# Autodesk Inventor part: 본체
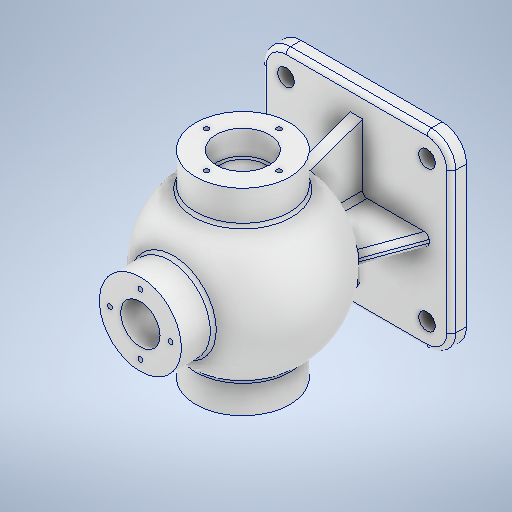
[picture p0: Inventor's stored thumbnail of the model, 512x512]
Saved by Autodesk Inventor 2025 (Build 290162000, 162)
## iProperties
Created: 2025-08
Part Number: 본체
Material: 알루미늄 6061
Document SubType Name: Modeling
Designer: infra017
Density: 2.7 g/cm^3
Appearance: 알루미늄 - 평지
Mass: 1529.39 g
Surface Area: 1220.4 cm^2
Volume: 566.442 cm^3
Author: infra017
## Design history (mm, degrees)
sketch "스케치1"
  geometry: L1 (-62.5, 62.5)-(62.5, 62.5); L2 (62.5, 62.5)-(62.5, -62.5); L3 (62.5, -62.5)-(-62.5, -62.5); L4 (-62.5, -62.5)-(-62.5, 62.5); L5 (-62.5, 62.5)-(62.5, -62.5); L6 (62.5, 62.5)-(-62.5, -62.5); 1 further point
  constraints: 12 end point, 2 midpoint, 2 parallel, 1 horizontal, 1 perpendicular
  dimensions: "d0" = 125 distance of L1.start L1.end; "d1" = 125 distance of L3.end L1.start
extrude "돌출1" new body sketch "스케치1" distance "d2" = 10; taper "d3" = 0 deg
node "작업 평면1"
sketch "스케치2"
  geometry: L1 (-54, 0.116)-(54, -0.116); A1 r 54 centre (0, 0) between (54, -0.116) and (-54, 0.116); 1 further point
  constraints: 2 end point, 2 point on circle, 1 centre point, 1 coincident
  dimensions: "d5" = 108 diameter of A1; "d6" = 108 distance of L1.start L1.end; "d7" = 107.99975 horizontal distance of L1.start L1.end
revolve "회전1" sketch "스케치2" stored, may be unused: angle "d8" = 90 deg
sketch "스케치3"
  geometry: L1 (-27, 152.563)-(27, 152.563); L2 (27, 152.563)-(27, 131.765); L3 (27, 131.765)-(-27, 131.765); L4 (-27, 131.765)-(-27, 152.563); L5 (0, 152.563)-(0, 131.765); L6 (-64.215, 116)-(-44.215, 116); L7 (-44.215, 116)-(-44.215, 54); L8 (-44.215, 54)-(-64.215, 54); L9 (-64.215, 54)-(-64.215, 116); L10 (44, 116)-(65.785, 116); L11 (65.785, 116)-(65.785, 54); L12 (65.785, 54)-(44, 54); L13 (44, 54)-(44, 116); L14 (-64.215, 85)-(-44.215, 85); L15 (44, 85)-(65.785, 85); L16 (62.5, 0)-(-62.5, 0) reference; A1 r 54 centre (0, 85) between (27, 131.765) and (-44.215, 54) reference; 8 further points
  constraints: 30 end point, 7 midpoint, 6 parallel, 3 horizontal, 3 perpendicular, 2 horizontal alignment, 2 point on circle, 1 coincident, 1 vertical alignment
  dimensions: "d9" = 54 distance of L1.start L1.end; "d10" = 20.79787 distance of L1.end L2.end; "d11" = 20 distance of L6.start L6.end; "d12" = 130 distance of L10.end L6.start; "d13" = 62 distance of L8.end L6.start; "d14" = 62 distance of L10.end L11.end; "d15" = 44 distance from line of point (0, 0) L13
revolve "회전2" stored, may be unused: angle "d16" = 90 deg
revolve "회전3" stored, may be unused: angle "d17" = 90 deg
sketch "스케치4"
  geometry: C1 r 17.5 at (0, 0); C2 r 31 at (0, 0) reference; 1 further point
  constraints: 1 centre point, 1 coincident
  dimensions: "d18" = 35 diameter of C1
extrude "돌출2" cut sketch "스케치4" distance "d19" = 16; taper "d20" = 0 deg
sketch "스케치5"
  geometry: C1 r 17.5 at (0, 0) reference; C2 r 17.5 at (0, 0); 1 further point
  constraints: 1 centre point, 1 coincident
extrude "돌출3" cut sketch "스케치5" distance "d21" = 16; taper "d22" = 0 deg
sketch "스케치6"
  geometry: C1 r 13 at (0, 0); 1 further point
  constraints: 1 centre point, 1 coincident
  dimensions: "d23" = 26 diameter of C1
extrude "돌출4" cut sketch "스케치6" distance "d24" = 28.5; taper "d25" = 0 deg
sketch "스케치7"
  geometry: L1 (-37.34, 44.04)-(-49.686, 10.121); L2 (35.742, 43.431)-(47.91, 10); L3 (-62.5, 0)-(-62.5, 10) reference; L4 (62.5, 0)-(62.5, 10) reference; L5 (-37.34, 44.04)-(-36.812, 45.492); L6 (35.742, 43.431)-(35.441, 44.258); L7 (-36.812, 45.492)-(35.441, 44.258); L8 (-49.686, 10.121)-(47.91, 10); L9 (-49.686, 10.121)-(47.91, 10); A1 r 54 centre (0, 85) between (-44.215, 54) and (-44.215, 116) reference; 2 further points; 1 other entity
  constraints: 14 end point, 2 point on circle, 2 point on line, 1 collinear, 1 midpoint, 1 other
  dimensions: "d28" = 20 deg angle of L3 L1; "d29" = 12 distance from line of L3.end L1; "d30" = 12 distance from line of point (62.5, 5) L2; "d31" = 20 deg angle of L4 L2
extrude "돌출5" join sketch "스케치7" stored distance "d32" = 8; taper "d33" = 0 deg
sketch "스케치8"
  geometry: L1 (-35.441, 44.258)-(-47.91, 10); L2 (62.5, 10)-(-62.5, 10) reference; L3 (35.441, 44.258)-(47.91, 10); L4 (-62.5, 0)-(-62.5, 10) reference; L5 (62.5, 0)-(62.5, 10) reference; L6 (-35.441, 44.258)-(35.441, 44.258); L7 (-47.91, 10)-(47.91, 10); A1 r 54 centre (0, 85) between (-27, 131.765) and (27, 131.765) reference; 3 further points
  constraints: 8 end point, 2 midpoint, 2 point on circle, 2 point on line, 1 collinear
  dimensions: "d34" = 20 deg angle of L4 L1; "d35" = 12 distance from line of point (-62.5, 5) L1; "d36" = 12 distance from line of point (62.5, 5) L3; "d37" = 20 deg angle of L5 L3
extrude "돌출6" join sketch "스케치8" stored distance "d38" = 8; taper "d39" = 0 deg
sketch "스케치9"
  geometry: L1 (46.5, -46.5)-(-46.5, -46.5); L2 (-46.5, -46.5)-(-46.5, 46.5); L3 (-46.5, 46.5)-(46.5, 46.5); L4 (46.5, 46.5)-(46.5, -46.5); L5 (46.5, -46.5)-(-46.5, 46.5); L6 (-46.5, -46.5)-(46.5, 46.5); 1 further point
  constraints: 12 end point, 2 midpoint, 2 parallel, 1 horizontal, 1 perpendicular
  dimensions: "d40" = 93 distance of L1.start L1.end; "d41" = 93 distance of L1.end L2.end
hole "구멍1" sketch "스케치9" at (46.5, -46.5), (-46.5, -46.5), (-46.5, 46.5), (46.5, 46.5) diameter "d42" = 11; stored, may be unused: countersink angle "d46" = 90 deg, drill point angle "d48" = 118 deg; dims "d43" = 6, "d44" = 4, "d45" = 2, "d47" = 8
sketch "스케치10"
  geometry: L1 (49.785, 102.5)-(49.785, 67.5) reference; L2 (44.215, 116)-(44.215, 54) reference; L3 (49.785, 100)-(44.215, 100); L4 (44.215, 100)-(44.215, 85); L5 (44.215, 85)-(49.785, 85); L6 (49.785, 85)-(49.785, 100); L7 (-44.215, 54)-(-44.215, 116) reference; L8 (-48.215, 67.5)-(-48.215, 102.5) reference; L9 (-44.215, 100)-(-48.215, 100); L10 (-48.215, 100)-(-48.215, 85); L11 (-48.215, 85)-(-44.215, 85); L12 (-44.215, 85)-(-44.215, 100); L13 (44.215, 100)-(44.215, 85); L14 (49.785, 100)-(49.785, 85); L15 (-44.215, 100)-(-44.215, 85); L16 (-48.215, 100)-(-48.215, 85); 5 further points
  constraints: 24 end point, 4 parallel, 3 collinear, 3 perpendicular, 2 horizontal, 2 midpoint, 2 point on line
  dimensions: "d49" = 15 distance between parallel lines of L5 L3; "d50" = 15 distance between parallel lines of L11 L9
revolve "회전4" sketch "스케치10" stored, may be unused: angle "d51" = 90 deg
sketch "스케치11"
  geometry: L1 (0, 44.258)-(0, 31) reference; L2 (0, 31)-(0, 44.258) reference; L3 (44.215, 116)-(44.215, 54) reference; L4 (-44.215, 54)-(-44.215, 116) reference; L5 (-27, 131.765)-(27, 131.765) reference; L6 (44.215, 85)-(-44.215, 85); C1 r 44 at (0, 85); A1 r 54 centre (0, 85) between (-36.812, 45.492) and (0, 31) reference; A2 r 54 centre (0, 85) between (0, 31) and (35.441, 44.258) reference; 3 further points
  constraints: 2 end point, 2 midpoint, 1 centre point, 1 coincident
  dimensions: "d52" = 88 diameter of C1
revolve "회전5" sketch "스케치11" stored, may be unused: angle "d55" = 360 deg
sketch "스케치12"
  geometry: C1 r 15 at (0, 0) reference; 1 further point
extrude "돌출7" cut sketch "스케치12" extent not by distance; stored distance "d56" = 0; taper "d57" = 0 deg
sketch "스케치13"
  geometry: L1 (0, 0)-(0, -24); C1 r 17.5 at (0, 0) reference; 8 further points
  constraints: 4 coincident, 2 end point, 1 vertical, 9 other
  dimensions: "d60" = 24 distance of L1.start L1.end; "d63" = 360 deg dimension on L1.start L1.end (derived)
hole "구멍2" sketch "스케치13" at (0, -24), (24, 0), (0, 24), (-24, 0) diameter "d65" = 3.242; stored, may be unused: countersink angle "d69" = 90 deg, drill point angle "d71" = 118 deg; dims "d66" = 12, "d67" = 4, "d68" = 2, "d70" = 15
sketch "스케치14"
  geometry: L1 (35.441, 0)-(0, 0) reference; L2 (0, 0)-(0, 20); L3 (0, 0)-(0, 35.441) reference; L4 (0, -36.812)-(0, 0) reference; L5 (35.441, 0)-(0, 0) reference; L6 (0, 0)-(0, 35.441) reference; L7 (0, 0)-(-35.441, 0) reference; L8 (-31, 44.215)-(31, 44.215) reference; L9 (31, -44.215)-(-31, -44.215) reference; L10 (4, 35.441)-(4, 4) reference; C1 r 13 at (0, 0) reference; C2 r 27 at (0, 0) reference; C3 r 27 at (0, 0) reference; 7 further points
  constraints: 4 coincident, 2 end point, 1 point on line, 9 other
  dimensions: "d75" = 20 distance of L1.end L2.end; "d78" = 360 deg dimension on C1.centre L2.end (derived)
hole "구멍3" sketch "스케치14" at (0, 20), (-20, 0), (0, -20), (20, 0) diameter "d80" = 3.242; stored, may be unused: countersink angle "d84" = 90 deg, drill point angle "d86" = 118 deg; dims "d81" = 9, "d82" = 4, "d83" = 2, "d85" = 11
fillet "모깎기1" dims "d87" = 3
fillet "모깎기2" dims "d88" = 3
fillet "모깎기3" dims "d89" = 3
fillet "모깎기4" dims "d90" = 3
fillet "모깎기5" dims "d91" = 16
fillet "모깎기6" dims "d92" = 3
fillet "모깎기7" dims "d93" = 3
fillet "모깎기8" dims "d94" = 3
node "솔리드1"
mirror "미러1"
node "투영된 루프1"
node "투영된 루프2"
node "투영된 루프3"
node "스케치 - 원형 패턴1" dims "d63" = 360 deg (derived)
node "투영된 루프4"
node "투영된 루프5"
node "스케치 - 원형 패턴2" dims "d78" = 360 deg (derived)
feature "A9D066F2-1C7D-4E18-AEED-F7BC21143FA4" dims "d42" = 11, "d43" = 6, "d44" = 4, "d45" = 2, "d46" = 90 deg, "d47" = 8, "d48" = 118 deg
other parameters: "d4" = 85
